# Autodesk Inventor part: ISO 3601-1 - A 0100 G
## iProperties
IsCustomPart: 0
Created: 2009-02
Part Number: ISO 3601-1 - A 0100 G
Material: Rubber
Description: Fluid power systems - O-ring
Document SubType Name: Modeling
Standard: ISO 3601-1
Designer: TRINH
Standard Revision: Third edition 2002-08-01
Standards Organization: ISO
Language: en-US
Size Designation: A 0100 G
Categories: <MemberInstance><Categories><Category DisplayName="Shaft Parts" InternalName="7f7aeb1f-a693-4053-b835-cee3144e0d98" Mnemonic="SHFT"><Category DisplayName="Seali
Density: 0.93 g/cm^3
Author: TRINH
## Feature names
1. Body [Revolution]
